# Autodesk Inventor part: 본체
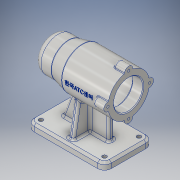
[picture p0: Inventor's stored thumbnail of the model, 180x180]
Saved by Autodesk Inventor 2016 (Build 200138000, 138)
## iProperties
Created: 2019-07
Part Number: 본체
Material: 알루미늄 6061
Document SubType Name: Modeling
Designer: 3sil_0101
Density: 2.7 g/cm^3
Appearance: 알루미늄 - 평지
Mass: 644.389 g
Surface Area: 654.106 cm^2
Volume: 238.662 cm^3
Author: 3sil_0101
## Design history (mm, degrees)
sketch "스케치1"
  geometry: L1 (56, 35)-(-56, 35); L2 (-56, 35)-(-56, -35); L3 (-56, -35)-(56, -35); L4 (56, -35)-(56, 35); L5 (56, 35)-(-56, -35); L6 (-56, 35)-(56, -35); 1 further point
  constraints: 12 end point, 2 midpoint, 2 parallel, 1 horizontal, 1 perpendicular
  dimensions: "d0" = 70 distance between parallel lines of L1 L3; "d1" = 112 distance between parallel lines of L4 L2
extrude "돌출1" new body sketch "스케치1" distance "d2" = 10; taper "d3" = 0 deg
fillet "모깎기1" dims "d4" = 10
sketch "스케치2"
  geometry: L1 (56, 10)-(56, 0) reference; L2 (-56, 0)-(-56, 10) reference; L3 (56, 80)-(-11, 80); L4 (-11, 80)-(-11, 110); L5 (-11, 110)-(56, 110); L6 (56, 110)-(56, 80); L7 (-11, 110)-(-31, 105); L8 (-31, 105)-(-31, 80); L9 (-31, 80)-(-11, 80); L10 (-31, 80)-(-56, 80); L11 (-56, 80)-(-56, 105); L12 (-56, 105)-(-31, 105); L13 (-31, 105)-(-31, 80); L14 (46, 0)-(-46, 0) reference; 1 further point
  constraints: 22 end point, 4 parallel, 2 collinear, 2 horizontal, 2 perpendicular, 1 vertical
  dimensions: "d7" = 112 distance between parallel lines of L6 L11; "d8" = 25 distance between parallel lines of L8 L11; "d9" = 45 distance between parallel lines of L11 L4; "d10" = 60 diameter of L5 L3; "d11" = 50 diameter of L12 L10; "d13" = 80 distance between parallel lines of L14 L3
revolve "회전1" sketch "스케치2" stored, may be unused: angle "d14" = 90 deg
sketch "스케치5"
  geometry: L1 (-4, -4)-(31, -4); L2 (31, -4)-(31, 4); L3 (31, 4)-(-4, 4); L4 (-4, 4)-(-4, -4); L5 (56, -25)-(56, 25) reference; L6 (-46, -35)-(46, -35) reference; L7 (-56, 25)-(-56, -25) reference; L8 (46, 35)-(-46, 35) reference; L9 (-46, -35)-(46, -35) reference; L10 (56, 0)-(-56, 0); L11 (0, 35)-(0, -35); A1 r 10 centre (46, -25) between (46, -35) and (56, -25) reference; A2 r 10 centre (-46, -25) between (-56, -25) and (-46, -35) reference; A3 r 10 centre (-46, 25) between (-46, 35) and (-56, 25) reference; A4 r 10 centre (46, 25) between (56, 25) and (46, 35) reference; 1 further point
  constraints: 12 end point, 4 midpoint, 2 parallel, 1 horizontal, 1 perpendicular, 1 other
  dimensions: "d28" = 25 distance between parallel lines of L5 L2; "d29" = 8 distance between parallel lines of L1 L3; "d54" = 4 distance between parallel lines of L11 L4
extrude "돌출3" join sketch "스케치5" stored distance "d30" = 10; taper "d31" = 0 deg
sketch "스케치6"
  geometry: L1 (56, 50)-(56, 110) reference; L2 (31, 50.268)-(-4, 50.268) reference; L3 (-11, 50)-(-11, 110) reference; L4 (-4, 50.268)-(31, 50.268) reference; L5 (31, 50.268)-(31, 50.268) reference; L6 (-56, 55)-(-56, 105) reference; L7 (-31, 55)-(-31, 105) reference; L8 (-11, 50)-(-11, 110) reference; L9 (-31, 55)-(-31, 105) reference; L10 (56, 50)-(56, 110) reference; L11 (56, 80)-(41, 80); L12 (41, 80)-(41, 101); L13 (41, 101)-(56, 101); L14 (56, 101)-(56, 80); L15 (41, 80)-(-13, 80); L16 (-13, 80)-(-13, 104); L17 (-13, 104)-(41, 104); L18 (41, 104)-(41, 80); L19 (-13, 80)-(-25, 80); L20 (-25, 80)-(-25, 101); L21 (-25, 101)-(-13, 101); L22 (-13, 101)-(-13, 80); L23 (-25, 80)-(-43, 80); L24 (-43, 80)-(-43, 97.5); L25 (-43, 97.5)-(-25, 97.5); L26 (-25, 97.5)-(-25, 80); L27 (-43, 80)-(-47, 80); L28 (-47, 80)-(-47, 96); L29 (-47, 96)-(-43, 96); L30 (-43, 96)-(-43, 80); L31 (-47, 80)-(-50, 80); L32 (-50, 80)-(-50, 90.5); L33 (-50, 90.5)-(-47, 90.5); L34 (-47, 90.5)-(-47, 80); L35 (-4, 50.268)-(-4, 50.268) reference; 1 further point
  constraints: 48 end point, 12 parallel, 6 horizontal, 6 perpendicular, 1 midpoint
  dimensions: "d32" = 42 diameter of L13 L11; "d33" = 48 diameter of L17 L15; "d34" = 15 distance between parallel lines of L1 L12; "d35" = 54 distance between parallel lines of L12 L16; "d36" = 42 diameter of L21 L19; "d37" = 12 distance between parallel lines of L16 L26; "d38" = 18 distance between parallel lines of L24 L26; "d39" = 4 distance between parallel lines of L24 L28; "d40" = 3 distance between parallel lines of L34 L32; "d41" = 35 diameter of L25 L23; "d42" = 32 diameter of L29 L27; "d43" = 21 diameter of L33 L31
revolve "회전2" sketch "스케치6" stored, may be unused: angle "d44" = 90 deg
sketch "스케치7"
  geometry: C1 r 21 at (0, 0) reference; C2 r 6 at (0, 30); 3 further points
  constraints: 3 vertical alignment, 1 centre point, 2 other
  dimensions: "d45" = 6 radius of C2
extrude "돌출4" join sketch "스케치7" distance "d46" = 16; taper "d47" = 0 deg
sketch "스케치8"
  geometry: L1 (10, 25)-(10, -25) reference; L2 (10, 35)-(10, 25) reference; L3 (10, 35)-(0, 35) reference; L4 (57.334, 19.654)-(10, 28); C1 r 21 at (80, 0) reference; A1 r 30 centre (80, 0) between (74.03, 29.4) and (50.6, 5.97) reference; A2 r 6 centre (50, 0) between (50.6, 5.97) and (50.6, -5.97) reference; A3 r 30 centre (80, 0) between (50.6, -5.97) and (74.03, -29.4) reference; A4 r 6 centre (80, -30) between (74.03, -29.4) and (85.97, -29.4) reference; A5 r 30 centre (80, 0) between (85.97, -29.4) and (109.4, -5.97) reference; A6 r 6 centre (110, 0) between (109.4, -5.97) and (109.4, 5.97) reference; A7 r 30 centre (80, 0) between (109.4, 5.97) and (85.97, 29.4) reference; A8 r 6 centre (80, 30) between (85.97, 29.4) and (74.03, 29.4) reference; A9 r 30 centre (80, 0) between (74.03, 29.4) and (50.6, 5.97) reference; 1 further point
  constraints: 2 end point, 2 point on circle, 1 point on line
  dimensions: "d52" = 7 distance from line of L3 L4.end; "d53" = 100 deg angle of L2 L4
feature "리브2" sketch "스케치8" dims "d55" = 1, "d56" = 8, "d57" = 0, "d58" = 0, "d59" = 1, "d60" = 1
sketch "스케치9"
  geometry: L1 (-31, 55)-(-11, 50) reference; L2 (46, 10)-(-46, 10) reference; L3 (-56, 10)-(-46, 10) reference; L4 (-56, 0)-(-56, 10) reference; L5 (-20.57, 52.393)-(-36, 10); 1 further point
  constraints: 2 end point, 2 point on line
  dimensions: "d61" = 110 deg angle of L2 L5; "d62" = 20 distance from line of L4 L5.end
feature "리브3" sketch "스케치9" dims "d63" = 1, "d64" = 8, "d65" = 0, "d66" = 0, "d67" = 1, "d68" = 1
chamfer "모따기1" distance "d69" = 3; stored, may be unused: second distance "d70" = 2, angle "d71" = 45 deg
fillet "모깎기4" dims "d74" = 3
fillet "모깎기5" dims "d75" = 10
fillet "모깎기6" dims "d76" = 3
chamfer "모따기2" distance "d77" = 1; stored, may be unused: second distance "d78" = 2, angle "d79" = 45 deg
fillet "모깎기7" dims "d80" = 3
sketch "스케치10"
  geometry: L1 (56, -25)-(56, 25) reference; L2 (-46, -35)-(46, -35) reference; L3 (-56, 25)-(-56, -25) reference; L4 (46, 35)-(-46, 35) reference; A1 r 10 centre (46, -25) between (46, -35) and (56, -25) reference; A2 r 10 centre (-46, -25) between (-56, -25) and (-46, -35) reference; A3 r 10 centre (-46, 25) between (-46, 35) and (-56, 25) reference; A4 r 10 centre (46, 25) between (56, 25) and (46, 35) reference; 5 further points
  constraints: 4 coincident
hole "구멍1" sketch "스케치10" at (-46, 25), (46, 25), (46, -25), (-46, -25) diameter "d82" = 6; stored, may be unused: countersink angle "d86" = 90 deg, drill point angle "d88" = 118 deg; dims "d83" = 6, "d84" = 4, "d85" = 2, "d87" = 8
fillet "모깎기9" dims "d97" = 3
fillet "모깎기10" dims "d98" = 0.3
fillet "모깎기11" dims "d99" = 3
node "작업 평면1"
sketch "스케치12"
  geometry: L1 (56, 85.97)-(56, 109.4) reference; L2 (56, 86)-(56, 74) reference; 4 further points
  constraints: 1 horizontal alignment, 1 midpoint, 1 other
  dimensions: "d101" = 42 distance from line of L1 point (14, 80)
feature "엠보싱1" sketch "스케치12" dims "d0" = 70, "d1" = 112, "d7" = 112, "d8" = 25, "d9" = 45, "d10" = 60, "d11" = 50, "d13" = 80, "d102" = 0.5, "d103" = 0
fillet "모깎기12" dims "d104" = 1
sketch "스케치13"
  geometry: C1 r 22 at (30, 0) reference; A1 r 1 centre (23.003, 30.2) between (23.229, 29.226) and (24.002, 30.171) reference; A2 r 30 centre (30, 0) between (23.229, 29.226) and (0.774, 6.771) reference; A3 r 1 centre (-0.2, 6.997) between (-0.171, 5.998) and (0.774, 6.771) reference; A4 r 6 centre (0, 0) between (-0.171, 5.998) and (-0.171, -5.998) reference; A5 r 1 centre (-0.2, -6.997) between (0.774, -6.771) and (-0.171, -5.998) reference; A6 r 30 centre (30, 0) between (0.774, -6.771) and (23.229, -29.226) reference; A7 r 1 centre (23.003, -30.2) between (24.002, -30.171) and (23.229, -29.226) reference; A8 r 6 centre (30, -30) between (24.002, -30.171) and (35.998, -30.171) reference; A9 r 1 centre (36.997, -30.2) between (36.771, -29.226) and (35.998, -30.171) reference; A10 r 30 centre (30, 0) between (36.771, -29.226) and (59.226, -6.771) reference; A11 r 1 centre (60.2, -6.997) between (60.171, -5.998) and (59.226, -6.771) reference; A12 r 6 centre (60, 0) between (60.171, -5.998) and (60.171, 5.998) reference; A13 r 1 centre (60.2, 6.997) between (59.226, 6.771) and (60.171, 5.998) reference; A14 r 30 centre (30, 0) between (59.226, 6.771) and (36.771, 29.226) reference; A15 r 1 centre (36.997, 30.2) between (35.998, 30.171) and (36.771, 29.226) reference; A16 r 6 centre (30, 30) between (35.998, 30.171) and (24.002, 30.171) reference; 2 further points
  constraints: 1 coincident
hole "구멍3" sketch "스케치13" at (30, 30) diameter "d105" = 3.242; stored, may be unused: countersink angle "d109" = 90 deg, drill point angle "d111" = 118 deg; dims "d106" = 8, "d107" = 4, "d108" = 2, "d110" = 11
fillet "모깎기14" dims "d119" = 3
fillet "모깎기15" dims "d120" = 3
node "솔리드1"
pattern_circular "원형 패턴1" dims angle "d49" = 360 deg
mirror "대칭1"
pattern_circular "원형 패턴2" dims angle "d113" = 360 deg
node "투영된 루프2"
node "투영된 루프3"
node "투영된 루프4"
node "투영된 루프5"
node "투영된 루프6"
node "투영된 루프7"
node "투영된 루프8"
node "투영된 루프10"
